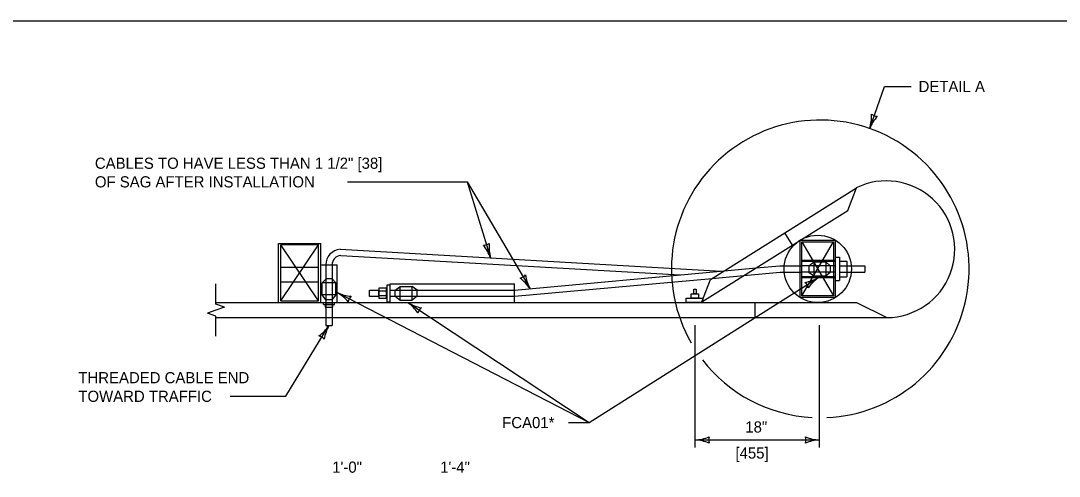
# Model space of a CAD drawing. Extents: x 49991.4 to 50021, y 49987.6 to 50011.4.
# Drawn here: x 50007.89 to 50013.47, y 49996.55 to 49999 of the extents above; entities that cross this region are included whole.
import ezdxf

# ---------------------------------------------------------------- set-up
doc = ezdxf.new("R2010")
doc.units = 0
for name, color, linetype in [('Level 1', 7, 'Continuous'), ('Level 2', 7, 'Continuous'), ('Level 3', 7, 'Continuous'), ('Level 4', 7, 'Continuous'), ('Level 6', 7, 'Continuous')]:
    doc.layers.add(name, color=color, linetype=linetype)

msp = doc.modelspace()

# ---------------------------------------------------------------- linework, layer by layer
at = {"layer": 'Level 1'}
for p, q in [((50011.592, 49997.6096), (50012.3764, 49998.1015)), ((50012.3304, 49997.9807), (50012.3764, 49998.1015)), ((50011.546, 49997.4888), (50012.3304, 49997.9807)), ((50011.9911, 49997.8599), (50012.0325, 49997.7939)), ((50009.271, 49997.4852), (50009.271, 49997.8034)), ((50009.271, 49997.8034), (50009.499, 49997.8034)), ((50009.486, 49997.795), (50009.2838, 49997.795)), ((50009.486, 49997.495), (50009.2838, 49997.795)), ((50009.2838, 49997.495), (50009.486, 49997.795)), ((50009.2838, 49997.495), (50009.2838, 49997.795)), ((50009.486, 49997.495), (50009.486, 49997.795)), ((50009.499, 49997.4852), (50009.499, 49997.8034)), ((50009.6024, 49997.7721), (50011.6495, 49997.6544)), ((50012.0842, 49997.8113), (50012.2541, 49997.5209)), ((50012.0842, 49997.5209), (50012.2541, 49997.8113)), ((50009.6058, 49997.739), (50011.43, 49997.6341)), ((50012.2633, 49997.7285), (50012.2866, 49997.7285)), ((50012.2866, 49997.7285), (50012.2866, 49997.6036)), ((50012.2866, 49997.7085), (50012.3252, 49997.7085)), ((50012.3252, 49997.7085), (50012.3252, 49997.6236)), ((50009.499, 49997.6879), (50009.5864, 49997.6879)), ((50009.5864, 49997.4852), (50009.5864, 49997.6879)), ((50010.5396, 49997.5519), (50011.6657, 49997.6558)), ((50011.8377, 49997.6718), (50011.9656, 49997.6835)), ((50011.9656, 49997.6835), (50012.0842, 49997.6835)), ((50012.2866, 49997.6835), (50012.4221, 49997.6835)), ((50012.4221, 49997.6835), (50012.4221, 49997.6486)), ((50010.5396, 49997.5189), (50011.6011, 49997.6154)), ((50011.546, 49997.4888), (50011.592, 49997.6096)), ((50011.7726, 49997.6309), (50011.9674, 49997.6486)), ((50011.9674, 49997.6486), (50012.0842, 49997.6486)), ((50012.2633, 49997.6036), (50012.2866, 49997.6036)), ((50012.2866, 49997.6486), (50012.4221, 49997.6486)), ((50012.2866, 49997.6236), (50012.3252, 49997.6236)), ((50009.8088, 49997.5519), (50009.81, 49997.5519)), ((50009.81, 49997.5479), (50009.851, 49997.5479)), ((50009.8722, 49997.5853), (50010.5396, 49997.5853)), ((50009.8722, 49997.4852), (50009.8722, 49997.5853)), ((50010.5396, 49997.4852), (50010.5396, 49997.5853)), ((50008.935, 49997.4852), (50012.3764, 49997.4852)), ((50009.271, 49997.4852), (50009.499, 49997.4852)), ((50009.2838, 49997.495), (50009.486, 49997.495)), ((50009.8088, 49997.5187), (50009.81, 49997.5187)), ((50009.81, 49997.5226), (50009.851, 49997.5226)), ((50011.8321, 49997.4045), (50011.8321, 49997.4852)), ((50012.3764, 49997.4852), (50012.5404, 49997.4045)), ((50008.935, 49997.4045), (50012.5404, 49997.4045)), ((50009.5258, 49997.4045), (50009.5258, 49997.3625)), ((50009.5593, 49997.4045), (50009.5593, 49997.3625)), ((50009.5258, 49997.3625), (50009.5592, 49997.3625))]:
    msp.add_line(p, q, dxfattribs=at)
for points in [[(49999.3835, 49998.9992), (50016.7501, 49998.9992), (50016.7501, 49987.7988), (49999.3835, 49987.7988)], [(50012.0842, 49997.8113), (50012.2541, 49997.8113), (50012.2541, 49997.5209), (50012.0842, 49997.5209)], [(50009.8088, 49997.5519), (50009.8088, 49997.5187), (50009.7602, 49997.5187), (50009.7602, 49997.5519)], [(50009.81, 49997.5634), (50009.81, 49997.5084), (50009.851, 49997.5084), (50009.851, 49997.5634)], [(50009.8528, 49997.5796), (50009.8528, 49997.4897), (50009.8722, 49997.4897), (50009.8722, 49997.5796)], [(50011.5024, 49997.5329), (50011.5024, 49997.5578), (50011.5156, 49997.5578), (50011.5156, 49997.5329)], [(50011.4622, 49997.486), (50011.4622, 49997.5094), (50011.5516, 49997.5094), (50011.5516, 49997.486)], [(50011.4892, 49997.5097), (50011.4892, 49997.5322), (50011.528, 49997.5322), (50011.528, 49997.5097)]]:
    msp.add_lwpolyline(points, close=True, dxfattribs=at)
msp.add_lwpolyline([(50012.075, 49997.6485), (50012.075, 49997.8205), (50012.2633, 49997.8205), (50012.2633, 49997.5117), (50012.075, 49997.5117), (50012.075, 49997.6485)], dxfattribs=at)
msp.add_circle((50012.1691, 49997.6661), 0.1809, dxfattribs=at)
for centre, radius, start, end in [((50012.5381, 49997.7718), 0.3673, 270.3591, 116.1219), ((50009.6114, 49997.6871), 0.0855, 96.0231, 179.4229), ((50009.6112, 49997.6874), 0.0519, 95.9636, 179.3909)]:
    msp.add_arc(centre, radius, start, end, dxfattribs=at)
at = {"layer": 'Level 3'}
for p, q in [((50012.4481, 49998.4203), (50012.5276, 49998.646)), ((50012.5276, 49998.646), (50012.6708, 49998.646)), ((50009.6424, 49998.1339), (50010.2846, 49998.1339)), ((50010.2846, 49998.1339), (50010.623, 49997.5596)), ((50010.2846, 49998.1339), (50010.4107, 49997.7256)), ((50010.9408, 49996.8405), (50012.1736, 49997.6199)), ((50009.5864, 49997.5389), (50010.9404, 49996.8405)), ((50009.9668, 49997.4852), (50010.9404, 49996.8405)), ((50009.3118, 49996.9817), (50009.5425, 49997.3625)), ((50011.5094, 49997.3645), (50011.5094, 49996.707)), ((50012.1786, 49996.707), (50012.1786, 49997.3645)), ((50009.0124, 49996.9817), (50009.3118, 49996.9817)), ((50010.8298, 49996.8405), (50010.9408, 49996.8405)), ((50011.5094, 49996.747), (50012.1786, 49996.747))]:
    msp.add_line(p, q, dxfattribs=at)
for centre, radius, start, end in [((50012.2248, 49998.4868), 0.233, 343.4203, 2.6702), ((50012.4907, 49998.5413), 0.0548, 232.7318, 268.4542), ((50012.1825, 49997.6661), 0.7996, 272.5835, 209.8019), ((50012.6546, 49998.3379), 0.2223, 138.049, 158.2325), ((50010.3729, 49997.8481), 0.0548, 269.2757, 304.998), ((50010.1917, 49997.6461), 0.233, 19.9642, 39.214), ((50010.6257, 49997.7823), 0.2223, 174.5929, 194.7764), ((50010.5579, 49997.6701), 0.0548, 282.6459, 318.3683), ((50010.4283, 49997.4316), 0.233, 33.3344, 52.5843), ((50010.819, 49997.6645), 0.2223, 187.9631, 208.1466), ((50012.0625, 49997.8125), 0.2223, 279.7967, 299.9802), ((50012.3078, 49997.4295), 0.233, 125.168, 144.4178), ((50009.4764, 49997.3457), 0.2223, 40.1711, 60.3546), ((50009.6829, 49997.751), 0.233, 245.5424, 264.7923), ((50012.0653, 49997.5513), 0.0548, 14.4795, 50.2018), ((50009.7003, 49997.4802), 0.0548, 134.8539, 170.5763), ((50009.8365, 49997.3051), 0.2223, 33.9442, 54.1277), ((50010.0857, 49997.6856), 0.233, 239.3155, 258.5654), ((50010.0737, 49997.4144), 0.0548, 128.627, 164.3494), ((50009.3572, 49997.4854), 0.2223, 306.2537, 326.4372), ((50009.7475, 49997.2518), 0.233, 151.625, 170.8748), ((50009.4761, 49997.2529), 0.0548, 40.9365, 76.6588), ((50012.1825, 49997.6661), 0.7996, 217.6111, 266.8513), ((50011.4979, 49996.9797), 0.233, 272.8273, 292.0772), ((50011.6376, 49996.747), 0.0548, 162.1388, 197.8612), ((50012.1877, 49996.9692), 0.2223, 247.456, 267.6395), ((50012.0504, 49996.747), 0.0548, 342.1388, 17.8612), ((50011.5002, 49996.5249), 0.2223, 67.456, 87.6395), ((50012.1901, 49996.5143), 0.233, 92.8273, 112.0772)]:
    msp.add_arc(centre, radius, start, end, dxfattribs=at)
at = {"layer": 'Level 4'}
for p, q in [((50012.0842, 49997.7122), (50012.2633, 49997.7122)), ((50012.0842, 49997.707), (50012.2633, 49997.707)), ((50009.2838, 49997.675), (50009.486, 49997.675)), ((50009.5258, 49997.6879), (50009.5258, 49997.4045)), ((50009.5593, 49997.6879), (50009.5593, 49997.4045)), ((50011.6657, 49997.6558), (50011.8377, 49997.6718)), ((50012.2633, 49997.6835), (50012.0842, 49997.6835)), ((50012.1216, 49997.6835), (50012.1482, 49997.7035)), ((50012.1216, 49997.6835), (50012.1216, 49997.6486)), ((50012.1482, 49997.7035), (50012.1482, 49997.6286)), ((50012.1482, 49997.7035), (50012.213, 49997.7035)), ((50012.213, 49997.7035), (50012.213, 49997.6286)), ((50012.213, 49997.7035), (50012.2352, 49997.6835)), ((50012.2352, 49997.6835), (50012.2352, 49997.6486)), ((50009.2838, 49997.5973), (50009.486, 49997.5973)), ((50009.506, 49997.5914), (50009.5272, 49997.6135)), ((50009.5592, 49997.6135), (50009.5272, 49997.6135)), ((50009.5802, 49997.5914), (50009.5592, 49997.6135)), ((50011.6008, 49997.6153), (50011.7726, 49997.6309)), ((50012.2633, 49997.6486), (50012.0842, 49997.6486)), ((50012.0842, 49997.6251), (50012.2633, 49997.6251)), ((50012.0842, 49997.6199), (50012.2633, 49997.6199)), ((50012.1216, 49997.6486), (50012.1482, 49997.6286)), ((50012.1482, 49997.6286), (50012.213, 49997.6286)), ((50012.213, 49997.6286), (50012.2352, 49997.6486)), ((50009.506, 49997.5265), (50009.506, 49997.5914)), ((50009.5802, 49997.5914), (50009.506, 49997.5914)), ((50009.5802, 49997.5265), (50009.5802, 49997.5914)), ((50009.8722, 49997.5519), (50010.5396, 49997.5519)), ((50009.8988, 49997.5522), (50009.9254, 49997.5724)), ((50009.8988, 49997.5188), (50009.8988, 49997.5522)), ((50009.9254, 49997.5724), (50009.9894, 49997.5724)), ((50009.9254, 49997.4974), (50009.9254, 49997.5724)), ((50010.016, 49997.5522), (50009.9894, 49997.5724)), ((50009.9894, 49997.4974), (50009.9894, 49997.5724)), ((50010.016, 49997.5188), (50010.016, 49997.5522)), ((50009.5802, 49997.5265), (50009.506, 49997.5265)), ((50009.526, 49997.5), (50009.506, 49997.5265)), ((50009.5132, 49997.4754), (50009.5132, 49997.4852)), ((50009.5588, 49997.5), (50009.526, 49997.5)), ((50009.5802, 49997.5265), (50009.5588, 49997.5)), ((50009.5718, 49997.4754), (50009.5718, 49997.4852)), ((50009.8722, 49997.5189), (50010.5396, 49997.5189)), ((50009.8988, 49997.5188), (50009.9254, 49997.4974)), ((50009.9254, 49997.4974), (50009.9894, 49997.4974)), ((50010.016, 49997.5188), (50009.9894, 49997.4974)), ((50009.5132, 49997.4754), (50009.5718, 49997.4754))]:
    msp.add_line(p, q, dxfattribs=at)
msp.add_lwpolyline([(50009.5216, 49997.4753), (50009.5216, 49997.4612), (50009.5634, 49997.4612), (50009.5634, 49997.4753)], close=True, dxfattribs=at)
at = {"layer": 'Level 6'}
for p, q in [((50008.935, 49997.4773), (50008.935, 49997.5852)), ((50008.935, 49997.4449), (50008.8893, 49997.4287)), ((50008.935, 49997.4125), (50008.8893, 49997.4287)), ((50008.9807, 49997.4611), (50008.935, 49997.4773)), ((50008.9807, 49997.4611), (50008.935, 49997.4449)), ((50008.935, 49997.3045), (50008.935, 49997.4125))]:
    msp.add_line(p, q, dxfattribs=at)

# ---------------------------------------------------------------- texts
at = {"layer": 'Level 2'}
for s, p in [('DETAIL A', (50012.7108, 49998.616)), ('CABLES TO HAVE LESS THAN 1 1/2" [38] ', (50008.2851, 49998.2039)), ('OF SAG AFTER INSTALLATION', (50008.2851, 49998.1039)), ('THREADED CABLE END', (50008.1961, 49997.0517)), ('TOWARD TRAFFIC', (50008.1961, 49996.9517)), ('FCA01*', (50010.4734, 49996.8105)), ('18"', (50011.7798, 49996.787)), ('[455]', (50011.7268, 49996.647)), ('1\'-0"', (50009.5602, 49996.5711)), ('1\'-4"', (50010.1402, 49996.5711))]:
    msp.add_text(s, height=0.06, dxfattribs=at).set_placement(p)

doc.saveas('drawing.dxf')
